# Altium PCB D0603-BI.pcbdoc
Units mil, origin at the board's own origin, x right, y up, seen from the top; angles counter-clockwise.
Board outline 620 x 553.72 mil, 2 copper layers (Top Layer, Bottom Layer), stack 0 mil thick; 1 components, 0 nets, 2 pads, 0 vias.
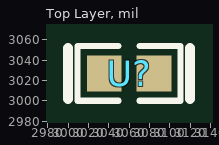
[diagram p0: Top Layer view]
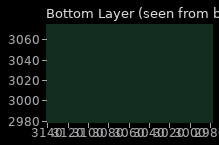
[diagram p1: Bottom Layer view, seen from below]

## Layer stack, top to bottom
Top Layer: signal copper (thickness not stored)
Bottom Layer: signal copper (thickness not stored)

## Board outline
3370,2750 2750,2750 2750,3303.72 3370,3303.72

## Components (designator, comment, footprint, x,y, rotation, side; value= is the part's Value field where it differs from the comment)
U? "" D0603-BI 3060,3026.86 r0 top

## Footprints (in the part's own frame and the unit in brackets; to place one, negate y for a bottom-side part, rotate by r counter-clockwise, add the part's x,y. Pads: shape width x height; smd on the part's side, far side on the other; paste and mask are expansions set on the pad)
D0603-BI [mil]
  rect 34.38x35.72 smd paste-3937.01 mask+2: 1(-24.47,0) 2(24.47,0)
  silkscreen extent -60,-27 60,27

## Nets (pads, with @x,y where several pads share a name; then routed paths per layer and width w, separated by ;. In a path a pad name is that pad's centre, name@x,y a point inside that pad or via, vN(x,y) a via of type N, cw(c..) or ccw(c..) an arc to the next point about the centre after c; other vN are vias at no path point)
pads on no net: U?.1 U?.2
